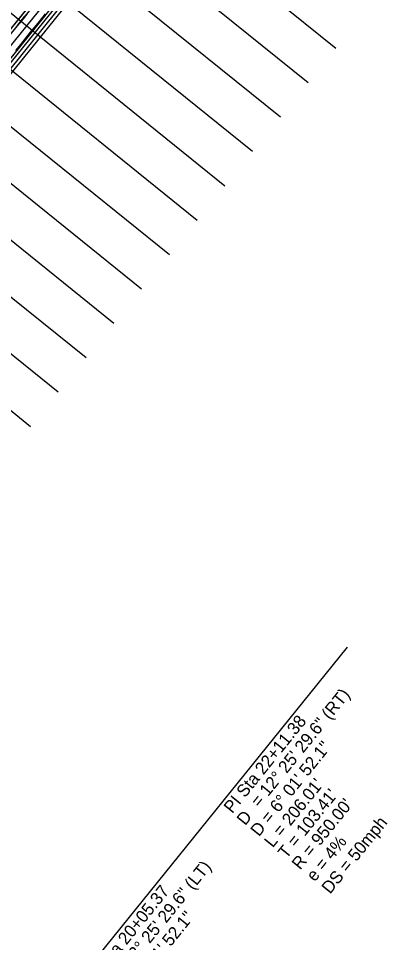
# Model space of a CAD drawing. Extents: x 2293233 to 2294507, y 892788 to 894229.
# Drawn here: x 2293959 to 2294168, y 893049 to 893572 of the extents above; entities that cross this region are included whole.
import ezdxf

# ---------------------------------------------------------------- set-up
doc = ezdxf.new("R2010")
doc.units = 0
for name, color, linetype in [('COGO Default Curve', 7, 'Continuous'), ('Prop EOT', 7, 'Continuous'), ('Prop Horizontal Alignment', 7, 'Continuous'), ('Prop Paved Shoulder', 7, 'Continuous'), ('Prop Roadway Bridge', 7, 'Continuous'), ('Scratch_Level_4', 7, 'Continuous')]:
    doc.layers.add(name, color=color, linetype=linetype)

msp = doc.modelspace()

# ---------------------------------------------------------------- linework, layer by layer
at = {"layer": 'COGO Default Curve'}
msp.add_line((2293767.71, 893325.15), (2294074.84, 893705.73), dxfattribs=at)
for points in [[(2294073.94, 893697.86), (2293868.79, 893443.63)], [(2293932.89, 893536.61), (2294046.75, 893677.72)], [(2293957.57, 893554.05), (2293959.66, 893556.64), (2293961.76, 893559.24), (2293963.85, 893561.83), (2293965.94, 893564.43), (2293968.04, 893567.02), (2293970.13, 893569.62), (2293972.22, 893572.21), (2293974.32, 893574.8)], [(2293957.62, 893566.86), (2293959.72, 893569.45), (2293961.81, 893572.05), (2293963.9, 893574.64)], [(2293958.48, 893568.32), (2293960.57, 893570.91), (2293962.67, 893573.51)], [(2293958.81, 893555.2), (2293960.91, 893557.79), (2293963, 893560.38), (2293965.09, 893562.98), (2293967.19, 893565.57), (2293969.28, 893568.17), (2293971.38, 893570.76), (2293973.47, 893573.36)]]:
    msp.add_lwpolyline(points, dxfattribs=at)
at = {"layer": 'Prop EOT'}
msp.add_line((2293772.37, 893321.38), (2294079.51, 893701.97), dxfattribs=at)
at = {"layer": 'Prop Horizontal Alignment'}
for p, q in [((2293763.04, 893328.92), (2294070.17, 893709.5)), ((2293763.04, 893328.92), (2294070.17, 893709.5)), ((2293828.53, 892824.42), (2294145.15, 893216.47))]:
    msp.add_line(p, q, dxfattribs=at)
at = {"layer": 'Prop Paved Shoulder'}
msp.add_line((2293773.93, 893320.13), (2294081.06, 893700.71), dxfattribs=at)
at = {"layer": 'Prop Roadway Bridge'}
msp.add_line((2293864.73, 893429.45), (2293992.76, 893588.1), dxfattribs=at)
at = {"layer": 'Scratch_Level_4'}
for p, q in [((2293708.32, 893261.12), (2294130.82, 893784.65)), ((2293905.11, 893743.82), (2294138.57, 893555.41)), ((2293889.41, 893724.36), (2294122.87, 893535.96)), ((2293873.71, 893704.91), (2294107.17, 893516.5)), ((2293858.01, 893685.45), (2294091.47, 893497.05)), ((2293842.31, 893666), (2294075.77, 893477.59)), ((2293826.61, 893646.54), (2294060.07, 893458.14)), ((2293810.91, 893627.09), (2294044.37, 893438.68)), ((2293795.21, 893607.63), (2294028.67, 893419.23)), ((2293779.51, 893588.18), (2294012.97, 893399.77)), ((2293763.81, 893568.72), (2293997.27, 893380.32)), ((2293748.11, 893549.27), (2293981.57, 893360.86)), ((2293732.41, 893529.81), (2293965.87, 893341.41))]:
    msp.add_line(p, q, dxfattribs=at)

# ---------------------------------------------------------------- texts
at = {"layer": 'Prop Horizontal Alignment'}
for s, p in [('= 12%%d 25\' 29.6" (RT)', (2294095.13, 893125.31)), ('PI Sta 22+11.38', (2294079.93, 893121.94)), ('D = 6%%d 01\' 52.1"', (2294095.06, 893108.85)), ("L = 206.01'", (2294102.84, 893102.56)), ("T = 103.41'", (2294110.62, 893096.28)), ("R = 950.00'", (2294118.4, 893090)), ('D', (2294087.28, 893115.13)), ('DS = 50mph', (2294135.27, 893076.37)), ('e = 4%', (2294126.63, 893083.35)), ('= 12%%d 25\' 29.6" (LT)', (2294017.66, 893029.08)), ('PI Sta 20+05.37', (2294002.46, 893025.71)), ('D = 6%%d 01\' 52.1"', (2294017.6, 893012.62))]:
    msp.add_text(s, height=7, rotation=51.0748, dxfattribs=at).set_placement(p)

doc.saveas('drawing.dxf')
